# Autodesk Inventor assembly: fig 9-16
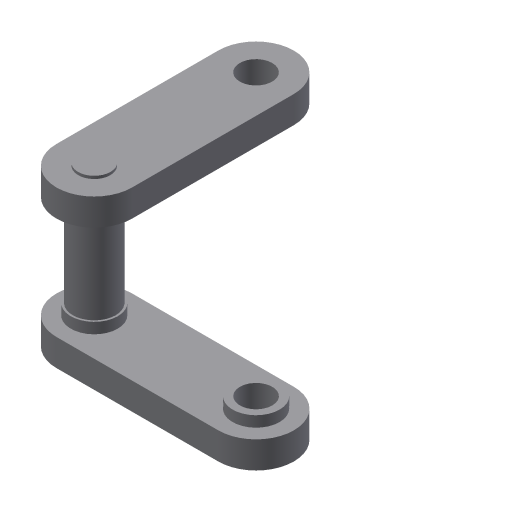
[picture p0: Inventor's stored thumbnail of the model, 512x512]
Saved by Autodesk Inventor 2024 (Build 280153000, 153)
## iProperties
Shininess: 64.0
Length Units: 11269
Angle Units: 11279
Time Units: 11290
Mass Units: 11283
Length Display Precision: 3
Angle Display Precision: 2
Created: 2002-01
Part Number: fig 9-16
Document SubType Name: Assembly
Designer: ***
Density: 0.0
Volumn: 0.0
Area: 0.0
PropertySet Name: Model Information
Control State: 0
Master: False
Checked Out: False
Author: ***
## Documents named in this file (3)
- D:\PROJECTS\Project 2023\RESOURCES INVENTOR 2024\RESOURCES INVENTOR 2024\Inventor_2023_Part\Inventor_2024_Part\c09_Inv_2024_prt\fig 9-16.iam
- D:\PROJECTS\Project 2023\RESOURCES INVENTOR 2024\RESOURCES INVENTOR 2024\Inventor_2023_Part\Inventor_2024_Part\c09_Inv_2024_prt\Part5.ipt
- D:\PROJECTS\Project 2023\RESOURCES INVENTOR 2024\RESOURCES INVENTOR 2024\Inventor_2023_Part\Inventor_2024_Part\c09_Inv_2024_prt\Part6.ipt
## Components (3 placed, 2 different names)
1. Part5:1 — Insert:1, Angle:1
2. Part6:1 — Insert:1, Insert:2
3. Part5:2 — Insert:2, Angle:1
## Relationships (3: Insert 2, Angle 1)
- Insert:1: Part5:1 ↔ Part6:1
- Insert:2: Part6:1 ↔ Part5:2
- Angle:1: Part5:1 ↔ Part5:2
